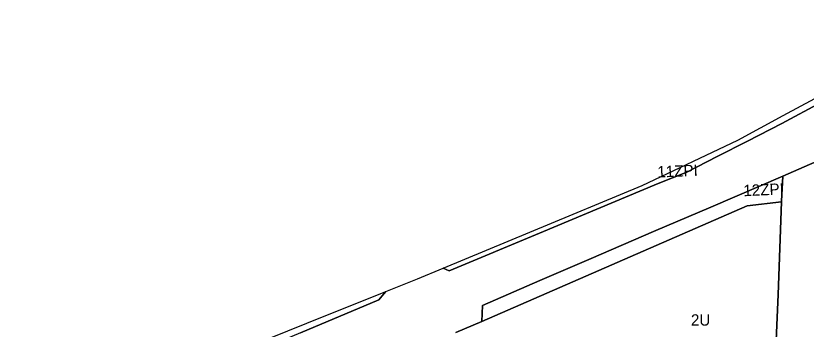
# Model space of a CAD drawing. Extents: x 7418021 to 7419743, y 5540231 to 5541685.
# Drawn here: x 7418068 to 7418764, y 5540950 to 5541227 of the extents above; entities that cross this region are included whole.
import ezdxf

# ---------------------------------------------------------------- set-up
doc = ezdxf.new("R2010")
doc.units = 0
doc.layers.add('linie_rozgraniczajace', color=7, linetype='Continuous')
doc.layers.add('oznaczenia_przeznaczen', color=7, linetype='Continuous')

msp = doc.modelspace()

# ---------------------------------------------------------------- linework, layer by layer
at = {"layer": 'linie_rozgraniczajace'}
for points in [[(7418826.39, 5541226.55), (7418814.18, 5541205.07), (7418801.97, 5541183.59), (7418789.83, 5541167.12), (7418777.69, 5541150.66), (7418742.75, 5541131.91), (7418712.48, 5541116.29), (7418685.89, 5541102.62), (7418659.3, 5541088.95), (7418633.99, 5541078.77), (7418529.23, 5541035.2), (7418449.78, 5541001.82), (7418444.4, 5541004.3), (7418520.87, 5541036.04), (7418619.89, 5541077.13), (7418704.01, 5541117.02), (7418743.95, 5541138.74), (7418783.9, 5541160.46), (7418808.95, 5541197.4), (7418825.59, 5541226.44), (7418825.81, 5541226.83)], [(7418743.74, 5541085.5), (7418742.67, 5541063.2), (7418742.65, 5541062.87), (7418712.28, 5541059.18), (7418478.64, 5540957.19), (7418479.03, 5540971.34), (7418529.67, 5540993.22), (7418574.77, 5541012.67), (7418629.76, 5541036.44), (7418680.33, 5541058.08)], [(7418393.97, 5540983.68), (7418392.2, 5540981.51), (7418387.85, 5540976.17), (7418318.78, 5540947.18), (7418249.71, 5540918.18), (7418231.54, 5540909.52), (7418230.9, 5540910.77), (7418230.26, 5540912.02), (7418157.63, 5540875.13), (7418118.14, 5540855.08), (7418094.31, 5540842.98), (7418086.26, 5540838.9), (7418085.93, 5540838.77), (7418085.59, 5540838.64), (7418079.4, 5540840.52), (7418073.21, 5540842.4), (7418070.21, 5540846.77), (7418067.99, 5540850.01), (7418141.34, 5540883.41), (7418164.76, 5540898.82), (7418195.88, 5540907.53), (7418227, 5540916.23), (7418324.43, 5540955.59), (7418389.45, 5540981.85)]]:
    msp.add_lwpolyline(points, close=True, dxfattribs=at)
for points in [[(7418318.78, 5540947.18), (7418387.85, 5540976.17), (7418392.2, 5540981.51), (7418393.97, 5540983.68), (7418421.86, 5540994.95), (7418444.4, 5541004.3), (7418449.78, 5541001.82), (7418529.23, 5541035.2), (7418633.99, 5541078.77), (7418659.3, 5541088.95), (7418685.89, 5541102.62), (7418712.48, 5541116.29), (7418742.75, 5541131.91), (7418777.69, 5541150.66)], [(7418780.85, 5541101.4), (7418762.43, 5541093.5), (7418743.74, 5541085.5), (7418680.33, 5541058.08), (7418629.76, 5541036.44), (7418574.77, 5541012.67), (7418529.67, 5540993.22), (7418479.03, 5540971.34), (7418478.64, 5540957.19), (7418455.77, 5540947.39)], [(7418764.77, 5540619.88), (7418764.16, 5540602.99), (7418763.54, 5540586.11), (7418763.38, 5540582.71), (7418763.21, 5540579.7), (7418763.03, 5540577.24), (7418753.15, 5540575.08), (7418743.27, 5540572.92), (7418731.8, 5540570.48), (7418720.33, 5540568.05), (7418720.42, 5540569.59), (7418729.09, 5540736.57), (7418739.59, 5540980.91), (7418742.65, 5541062.87), (7418742.67, 5541063.2), (7418743.74, 5541085.5), (7418762.43, 5541093.5), (7418780.85, 5541101.4)], [(7418455.77, 5540947.39), (7418478.64, 5540957.19), (7418712.28, 5541059.18), (7418742.65, 5541062.87), (7418739.59, 5540980.91), (7418729.09, 5540736.57)]]:
    msp.add_lwpolyline(points, dxfattribs=at)

# ---------------------------------------------------------------- texts
at = {"layer": 'oznaczenia_przeznaczen'}
for s, rotation, p in [('11ZPI', 2.66896, (7418633.36, 5541084.08)), ('12ZPI', 2.66896, (7418709.17, 5541067.63)), ('2U', 359.9118, (7418662.75, 5540953.55))]:
    msp.add_text(s, height=10, rotation=rotation, dxfattribs=at).set_placement(p)

doc.saveas('drawing.dxf')
